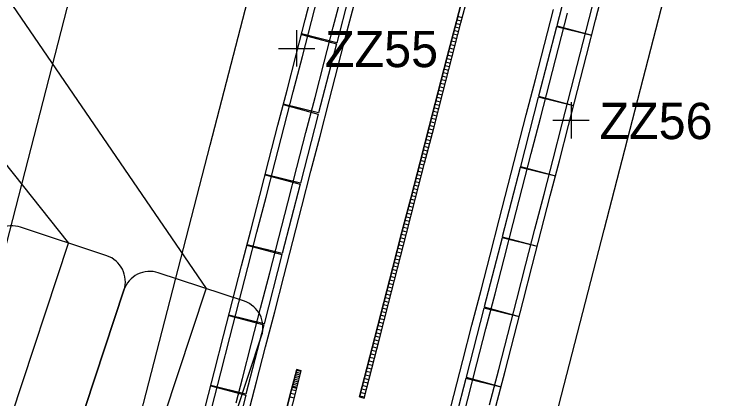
# Model space of a CAD drawing. Extents: x -733601 to -733291, y -1137892 to -1137187.
# Drawn here: x -733444.38 to -733424.52, y -1137642.25 to -1137631.66 of the extents above; entities that cross this region are included whole.
import ezdxf

# ---------------------------------------------------------------- set-up
doc = ezdxf.new("R2010")
doc.units = 0
for name, color, linetype in [('BP_ZBP_a_ZZ', 7, 'Continuous'), ('Default', 7, 'Continuous'), ('SIT_PROJ', 7, 'Continuous'), ('SIT_PUV_ZELEZNICE', 7, 'Continuous')]:
    doc.layers.add(name, color=color, linetype=linetype)

# ---------------------------------------------------------------- blocks, each defined once
blk = doc.blocks.new('T_PS_1_3')
at = {"layer": 'Default'}
blk.add_line((-12.486, 3.717), (12.486, 3.717), dxfattribs=at)
for points in [[(10.986, 8), (-10.986, 8)], [(-12.486, 6.5), (-12.486, 1.5)], [(12.486, 1.5), (12.486, 6.5)], [(-10.986, 0), (10.986, 0)]]:
    blk.add_lwpolyline(points, dxfattribs=at)
for centre, start, end in [((-10.986, 6.5), 90, 180), ((10.986, 6.5), 0, 90), ((-10.986, 1.5), 180, 270), ((10.986, 1.5), 270, 360)]:
    blk.add_arc(centre, 1.5, start, end, dxfattribs=at)
blk.add_text('SO', height=2.7, dxfattribs=at).set_placement((-11.75, 4.466))
blk = doc.blocks.new('T_PS_1_1_5')
at = {"layer": 'Default'}
blk.add_line((-12.486, 3.717), (12.486, 3.717), dxfattribs=at)
for points in [[(10.986, 8), (-10.986, 8)], [(-12.486, 6.5), (-12.486, 1.5)], [(12.486, 1.5), (12.486, 6.5)], [(-10.986, 0), (10.986, 0)]]:
    blk.add_lwpolyline(points, dxfattribs=at)
for centre, start, end in [((-10.986, 6.5), 90, 180), ((10.986, 6.5), 0, 90), ((-10.986, 1.5), 180, 270), ((10.986, 1.5), 270, 360)]:
    blk.add_arc(centre, 1.5, start, end, dxfattribs=at)
blk.add_text('SO', height=2.7, dxfattribs=at).set_placement((-11.75, 4.466))

msp = doc.modelspace()

# ---------------------------------------------------------------- linework, layer by layer
at = {"layer": 'BP_ZBP_a_ZZ'}
for p, q in [((-733436.599, -1137632.096), (-733436.599, -1137633.096)), ((-733437.099, -1137632.596), (-733436.099, -1137632.596)), ((-733429.027, -1137634.079), (-733429.027, -1137635.079)), ((-733429.527, -1137634.579), (-733428.527, -1137634.579))]:
    msp.add_line(p, q, dxfattribs=at)
at = {"layer": 'SIT_PROJ'}
for points in [[(-733455.227, -1137615.669), (-733439.093, -1137639.217), (-733439.093, -1137639.217)], [(-733457.665, -1137619.387), (-733442.89, -1137637.96), (-733442.89, -1137637.96)]]:
    msp.add_lwpolyline(points, dxfattribs=at)
at = {"layer": 'SIT_PUV_ZELEZNICE'}
for p, q in [((-733428.932, -1137630.069), (-733429.425, -1137631.976)), ((-733434.999, -1137630.535), (-733435.494, -1137632.442)), ((-733432.029, -1137631.753), (-733432.155, -1137631.72)), ((-733432.08, -1137631.946), (-733432.205, -1137631.914)), ((-733432.055, -1137631.849), (-733432.18, -1137631.817)), ((-733429.425, -1137631.976), (-733428.459, -1137632.236)), ((-733432.13, -1137632.14), (-733432.256, -1137632.107)), ((-733432.105, -1137632.043), (-733432.231, -1137632.011)), ((-733429.432, -1137632.005), (-733429.925, -1137633.913)), ((-733428.461, -1137632.246), (-733429.432, -1137632.005)), ((-733436.467, -1137632.21), (-733435.501, -1137632.47)), ((-733435.494, -1137632.442), (-733436.464, -1137632.2)), ((-733432.205, -1137632.43), (-733432.331, -1137632.398)), ((-733432.18, -1137632.334), (-733432.306, -1137632.301)), ((-733432.155, -1137632.237), (-733432.281, -1137632.204)), ((-733435.501, -1137632.47), (-733435.995, -1137634.377)), ((-733432.255, -1137632.624), (-733432.381, -1137632.591)), ((-733432.23, -1137632.527), (-733432.356, -1137632.495)), ((-733432.305, -1137632.818), (-733432.431, -1137632.785)), ((-733432.28, -1137632.721), (-733432.406, -1137632.688)), ((-733432.355, -1137633.011), (-733432.481, -1137632.979)), ((-733432.33, -1137632.914), (-733432.456, -1137632.882)), ((-733432.405, -1137633.205), (-733432.531, -1137633.172)), ((-733432.38, -1137633.108), (-733432.506, -1137633.076)), ((-733432.455, -1137633.398), (-733432.581, -1137633.366)), ((-733432.43, -1137633.302), (-733432.556, -1137633.269)), ((-733432.506, -1137633.592), (-733432.631, -1137633.56)), ((-733432.481, -1137633.495), (-733432.606, -1137633.463)), ((-733432.556, -1137633.786), (-733432.682, -1137633.753)), ((-733432.531, -1137633.689), (-733432.657, -1137633.656)), ((-733432.606, -1137633.979), (-733432.732, -1137633.947)), ((-733432.581, -1137633.882), (-733432.707, -1137633.85)), ((-733429.932, -1137633.942), (-733430.425, -1137635.849)), ((-733428.962, -1137634.182), (-733429.932, -1137633.942)), ((-733429.925, -1137633.913), (-733428.959, -1137634.172)), ((-733436.968, -1137634.146), (-733436.003, -1137634.406)), ((-733435.995, -1137634.377), (-733436.966, -1137634.136)), ((-733432.656, -1137634.173), (-733432.782, -1137634.14)), ((-733432.631, -1137634.076), (-733432.757, -1137634.044)), ((-733432.706, -1137634.367), (-733432.832, -1137634.334)), ((-733432.681, -1137634.27), (-733432.807, -1137634.237)), ((-733436.003, -1137634.406), (-733436.496, -1137636.313)), ((-733432.756, -1137634.56), (-733432.882, -1137634.528)), ((-733432.731, -1137634.463), (-733432.857, -1137634.431)), ((-733432.806, -1137634.754), (-733432.932, -1137634.721)), ((-733432.781, -1137634.657), (-733432.907, -1137634.625)), ((-733432.856, -1137634.947), (-733432.982, -1137634.915)), ((-733432.831, -1137634.851), (-733432.957, -1137634.818)), ((-733432.906, -1137635.141), (-733433.032, -1137635.109)), ((-733432.881, -1137635.044), (-733433.007, -1137635.012)), ((-733432.956, -1137635.335), (-733433.082, -1137635.302)), ((-733432.931, -1137635.238), (-733433.057, -1137635.205)), ((-733433.006, -1137635.528), (-733433.132, -1137635.496)), ((-733432.981, -1137635.432), (-733433.107, -1137635.399)), ((-733433.057, -1137635.722), (-733433.182, -1137635.689)), ((-733433.032, -1137635.625), (-733433.157, -1137635.593)), ((-733433.107, -1137635.916), (-733433.233, -1137635.883)), ((-733433.082, -1137635.819), (-733433.207, -1137635.786)), ((-733430.433, -1137635.878), (-733430.925, -1137637.786)), ((-733429.462, -1137636.119), (-733430.433, -1137635.878)), ((-733430.425, -1137635.849), (-733429.459, -1137636.109)), ((-733437.469, -1137636.082), (-733436.504, -1137636.342)), ((-733436.496, -1137636.313), (-733437.467, -1137636.072)), ((-733433.157, -1137636.109), (-733433.283, -1137636.077)), ((-733433.132, -1137636.012), (-733433.258, -1137635.98)), ((-733436.504, -1137636.342), (-733436.996, -1137638.249)), ((-733433.232, -1137636.4), (-733433.358, -1137636.367)), ((-733433.207, -1137636.303), (-733433.333, -1137636.27)), ((-733433.182, -1137636.206), (-733433.308, -1137636.174)), ((-733433.282, -1137636.593), (-733433.408, -1137636.561)), ((-733433.257, -1137636.496), (-733433.383, -1137636.464)), ((-733433.332, -1137636.787), (-733433.458, -1137636.754)), ((-733433.307, -1137636.69), (-733433.433, -1137636.658)), ((-733433.382, -1137636.981), (-733433.508, -1137636.948)), ((-733433.357, -1137636.884), (-733433.483, -1137636.851)), ((-733433.432, -1137637.174), (-733433.558, -1137637.142)), ((-733433.407, -1137637.077), (-733433.533, -1137637.045)), ((-733433.482, -1137637.368), (-733433.608, -1137637.335)), ((-733433.457, -1137637.271), (-733433.583, -1137637.239)), ((-733433.532, -1137637.561), (-733433.658, -1137637.529)), ((-733433.507, -1137637.465), (-733433.633, -1137637.432)), ((-733433.582, -1137637.755), (-733433.708, -1137637.723)), ((-733433.557, -1137637.658), (-733433.683, -1137637.626)), ((-733433.632, -1137637.949), (-733433.758, -1137637.916)), ((-733433.607, -1137637.852), (-733433.733, -1137637.819)), ((-733430.933, -1137637.815), (-733431.425, -1137639.722)), ((-733429.962, -1137638.055), (-733430.933, -1137637.815)), ((-733430.925, -1137637.786), (-733429.96, -1137638.045)), ((-733437.97, -1137638.018), (-733437.004, -1137638.278)), ((-733436.996, -1137638.249), (-733437.967, -1137638.009)), ((-733433.682, -1137638.142), (-733433.808, -1137638.11)), ((-733433.657, -1137638.046), (-733433.783, -1137638.013)), ((-733437.004, -1137638.278), (-733437.496, -1137640.186)), ((-733433.732, -1137638.336), (-733433.858, -1137638.304)), ((-733433.707, -1137638.239), (-733433.833, -1137638.207)), ((-733433.782, -1137638.53), (-733433.908, -1137638.497)), ((-733433.757, -1137638.433), (-733433.883, -1137638.4)), ((-733433.832, -1137638.723), (-733433.958, -1137638.691)), ((-733433.807, -1137638.626), (-733433.933, -1137638.594)), ((-733433.882, -1137638.917), (-733434.008, -1137638.884)), ((-733433.857, -1137638.82), (-733433.983, -1137638.788)), ((-733433.932, -1137639.111), (-733434.058, -1137639.078)), ((-733433.907, -1137639.014), (-733434.033, -1137638.981)), ((-733433.982, -1137639.304), (-733434.108, -1137639.272)), ((-733433.957, -1137639.207), (-733434.083, -1137639.175)), ((-733434.032, -1137639.498), (-733434.158, -1137639.465)), ((-733434.007, -1137639.401), (-733434.133, -1137639.369)), ((-733434.082, -1137639.692), (-733434.208, -1137639.659)), ((-733434.057, -1137639.595), (-733434.183, -1137639.562)), ((-733431.425, -1137639.722), (-733430.46, -1137639.982)), ((-733437.496, -1137640.186), (-733438.467, -1137639.945)), ((-733434.132, -1137639.885), (-733434.258, -1137639.853)), ((-733434.107, -1137639.788), (-733434.233, -1137639.756)), ((-733431.433, -1137639.751), (-733431.926, -1137641.658)), ((-733430.462, -1137639.992), (-733431.433, -1137639.751)), ((-733438.47, -1137639.955), (-733437.504, -1137640.214)), ((-733434.207, -1137640.176), (-733434.333, -1137640.143)), ((-733434.182, -1137640.079), (-733434.308, -1137640.046)), ((-733434.157, -1137639.982), (-733434.283, -1137639.95)), ((-733437.504, -1137640.214), (-733437.996, -1137642.122)), ((-733434.258, -1137640.369), (-733434.383, -1137640.337)), ((-733434.233, -1137640.272), (-733434.358, -1137640.24)), ((-733434.308, -1137640.563), (-733434.433, -1137640.53)), ((-733434.283, -1137640.466), (-733434.408, -1137640.434)), ((-733434.358, -1137640.757), (-733434.483, -1137640.724)), ((-733434.333, -1137640.66), (-733434.458, -1137640.627)), ((-733434.408, -1137640.95), (-733434.533, -1137640.918)), ((-733434.383, -1137640.853), (-733434.508, -1137640.821)), ((-733434.458, -1137641.144), (-733434.583, -1137641.111)), ((-733434.433, -1137641.047), (-733434.558, -1137641.015)), ((-733434.508, -1137641.338), (-733434.633, -1137641.305)), ((-733434.483, -1137641.241), (-733434.608, -1137641.208)), ((-733436.49, -1137641.55), (-733436.616, -1137641.517)), ((-733436.478, -1137641.501), (-733436.603, -1137641.469)), ((-733436.597, -1137641.445), (-733436.471, -1137641.477)), ((-733434.558, -1137641.531), (-733434.683, -1137641.499)), ((-733434.533, -1137641.434), (-733434.658, -1137641.402)), ((-733436.54, -1137641.743), (-733436.666, -1137641.711)), ((-733436.528, -1137641.695), (-733436.653, -1137641.662)), ((-733436.515, -1137641.646), (-733436.641, -1137641.614)), ((-733436.503, -1137641.598), (-733436.628, -1137641.565)), ((-733434.608, -1137641.725), (-733434.733, -1137641.692)), ((-733434.583, -1137641.628), (-733434.708, -1137641.596)), ((-733431.933, -1137641.688), (-733432.426, -1137643.595)), ((-733430.962, -1137641.928), (-733431.933, -1137641.688)), ((-733431.926, -1137641.658), (-733430.96, -1137641.918)), ((-733438.969, -1137641.892), (-733438.003, -1137642.151)), ((-733437.996, -1137642.122), (-733438.966, -1137641.882)), ((-733436.722, -1137641.929), (-733436.596, -1137641.961)), ((-733436.59, -1137641.937), (-733436.716, -1137641.904)), ((-733436.577, -1137641.888), (-733436.703, -1137641.856)), ((-733436.565, -1137641.84), (-733436.691, -1137641.808)), ((-733436.553, -1137641.792), (-733436.678, -1137641.759)), ((-733434.658, -1137641.918), (-733434.783, -1137641.886)), ((-733434.633, -1137641.822), (-733434.758, -1137641.789)), ((-733436.641, -1137642.133), (-733436.766, -1137642.101)), ((-733436.616, -1137642.036), (-733436.741, -1137642.004)), ((-733434.708, -1137642.112), (-733434.833, -1137642.08)), ((-733434.683, -1137642.015), (-733434.808, -1137641.983)), ((-733438.003, -1137642.151), (-733438.494, -1137644.058)), ((-733436.666, -1137642.23), (-733436.791, -1137642.197)), ((-733434.866, -1137642.201), (-733434.74, -1137642.233)), ((-733434.865, -1137642.201), (-733434.739, -1137642.233)), ((-733434.733, -1137642.209), (-733434.858, -1137642.176))]:
    msp.add_line(p, q, dxfattribs=at)
for points in [[(-733459.36, -1137757.582), (-733458.338, -1137753.729), (-733455.783, -1137744.061), (-733453.237, -1137734.391), (-733450.698, -1137724.719), (-733448.167, -1137715.044), (-733445.645, -1137705.368), (-733443.13, -1137695.689), (-733440.624, -1137686.008), (-733440.158, -1137684.204), (-733438.123, -1137676.326), (-733435.622, -1137666.644), (-733433.121, -1137656.962), (-733430.62, -1137647.279), (-733428.119, -1137637.597), (-733425.618, -1137627.915), (-733423.422, -1137619.411), (-733423.117, -1137618.233), (-733420.616, -1137608.551), (-733418.11, -1137598.87), (-733415.599, -1137589.19), (-733413.078, -1137579.513), (-733412.782, -1137578.384)], [(-733469.582, -1137755.14), (-733468.663, -1137751.534), (-733466.195, -1137741.843), (-733463.726, -1137732.153), (-733461.257, -1137722.462), (-733458.789, -1137712.772), (-733456.32, -1137703.081), (-733453.852, -1137693.391), (-733451.383, -1137683.701), (-733451.044, -1137682.371), (-733448.914, -1137674.01), (-733446.443, -1137664.32), (-733443.966, -1137654.632), (-733441.48, -1137644.946), (-733438.982, -1137635.263), (-733436.47, -1137625.584), (-733433.94, -1137615.909), (-733431.39, -1137606.239), (-733431.038, -1137604.913), (-733428.815, -1137596.577), (-733426.217, -1137586.92), (-733424.808, -1137581.736)], [(-733473.591, -1137751.638), (-733472.603, -1137747.76), (-733470.135, -1137738.069), (-733467.666, -1137728.379), (-733465.198, -1137718.688), (-733462.729, -1137708.998), (-733460.26, -1137699.307), (-733457.792, -1137689.617), (-733455.323, -1137679.926), (-733452.855, -1137670.236), (-733450.386, -1137660.545), (-733448.734, -1137654.061), (-733447.917, -1137650.855), (-733445.432, -1137641.168), (-733442.928, -1137631.487), (-733440.405, -1137621.811), (-733437.862, -1137612.139), (-733437.8, -1137611.906), (-733435.314, -1137602.469), (-733432.775, -1137592.797), (-733432.613, -1137592.177)], [(-733439.115, -1137642.457), (-733438.865, -1137641.489), (-733438.616, -1137640.521), (-733438.366, -1137639.553), (-733438.116, -1137638.585), (-733437.866, -1137637.617), (-733437.616, -1137636.649), (-733437.365, -1137635.681), (-733437.115, -1137634.713), (-733436.864, -1137633.745), (-733436.614, -1137632.777), (-733436.363, -1137631.81), (-733436.112, -1137630.842)], [(-733438.94, -1137642.502), (-733438.691, -1137641.534), (-733438.441, -1137640.566), (-733438.192, -1137639.598), (-733437.942, -1137638.63), (-733437.692, -1137637.662), (-733437.441, -1137636.694), (-733437.191, -1137635.726), (-733436.941, -1137634.758), (-733436.69, -1137633.79), (-733436.439, -1137632.822), (-733436.189, -1137631.855), (-733435.937, -1137630.887)], [(-733431.941, -1137630.892), (-733432.191, -1137631.859), (-733432.442, -1137632.827), (-733432.692, -1137633.794), (-733432.942, -1137634.761), (-733433.192, -1137635.728), (-733433.443, -1137636.696), (-733433.693, -1137637.663), (-733433.943, -1137638.63), (-733434.192, -1137639.598), (-733434.442, -1137640.565), (-733434.865, -1137642.201), (-733434.74, -1137642.233), (-733434.739, -1137642.233), (-733434.316, -1137640.598), (-733434.067, -1137639.63), (-733433.817, -1137638.663), (-733433.567, -1137637.695), (-733433.317, -1137636.728), (-733433.067, -1137635.761), (-733432.816, -1137634.793), (-733432.566, -1137633.826), (-733432.316, -1137632.859), (-733432.066, -1137631.892), (-733431.815, -1137630.925)], [(-733434.865, -1137642.201), (-733434.442, -1137640.565), (-733434.192, -1137639.598), (-733433.943, -1137638.63), (-733433.693, -1137637.663), (-733433.443, -1137636.696), (-733433.192, -1137635.728), (-733432.942, -1137634.761), (-733432.692, -1137633.794), (-733432.442, -1137632.827), (-733432.191, -1137631.859), (-733431.941, -1137630.892)], [(-733434.739, -1137642.233), (-733434.316, -1137640.598), (-733434.067, -1137639.63), (-733433.817, -1137638.663), (-733433.567, -1137637.695), (-733433.317, -1137636.728), (-733433.067, -1137635.761), (-733432.816, -1137634.793), (-733432.566, -1137633.826), (-733432.316, -1137632.859), (-733432.066, -1137631.892), (-733431.815, -1137630.925)], [(-733431.274, -1137642.414), (-733431.024, -1137641.447), (-733430.774, -1137640.48), (-733430.525, -1137639.513), (-733430.275, -1137638.546), (-733430.025, -1137637.58), (-733429.775, -1137636.613), (-733429.526, -1137635.646), (-733429.276, -1137634.679), (-733429.026, -1137633.712), (-733428.777, -1137632.746), (-733428.527, -1137631.779), (-733428.277, -1137630.812)], [(-733431.1, -1137642.459), (-733430.85, -1137641.492), (-733430.6, -1137640.525), (-733430.35, -1137639.558), (-733430.101, -1137638.591), (-733429.851, -1137637.625), (-733429.601, -1137636.658), (-733429.351, -1137635.691), (-733429.102, -1137634.724), (-733428.852, -1137633.757), (-733428.602, -1137632.791), (-733428.353, -1137631.824), (-733428.103, -1137630.857)], [(-733438.263, -1137642.358), (-733438.09, -1137641.688), (-733437.841, -1137640.72), (-733437.591, -1137639.753), (-733437.341, -1137638.785), (-733437.091, -1137637.817), (-733436.841, -1137636.849), (-733436.591, -1137635.881), (-733436.341, -1137634.913), (-733436.09, -1137633.946), (-733435.839, -1137632.978), (-733435.588, -1137632.01), (-733435.337, -1137631.043)], [(-733437.876, -1137642.458), (-733437.703, -1137641.788), (-733437.454, -1137640.82), (-733437.204, -1137639.852), (-733436.954, -1137638.885), (-733436.704, -1137637.917), (-733436.454, -1137636.949), (-733436.204, -1137635.981), (-733435.953, -1137635.014), (-733435.703, -1137634.046), (-733435.452, -1137633.078), (-733435.201, -1137632.111), (-733434.95, -1137631.143)], [(-733432.684, -1137643.796), (-733432.511, -1137643.126), (-733432.261, -1137642.159), (-733432.012, -1137641.192), (-733431.762, -1137640.225), (-733431.512, -1137639.258), (-733431.262, -1137638.291), (-733431.013, -1137637.324), (-733430.763, -1137636.358), (-733430.513, -1137635.391), (-733430.264, -1137634.424), (-733430.014, -1137633.457), (-733429.764, -1137632.491), (-733429.514, -1137631.524)], [(-733432.297, -1137643.896), (-733432.124, -1137643.226), (-733431.874, -1137642.259), (-733431.624, -1137641.292), (-733431.375, -1137640.325), (-733431.125, -1137639.358), (-733430.875, -1137638.391), (-733430.625, -1137637.425), (-733430.376, -1137636.458), (-733430.126, -1137635.491), (-733429.876, -1137634.524), (-733429.627, -1137633.557), (-733429.377, -1137632.591), (-733429.127, -1137631.624)], [(-733441.106, -1137659.005), (-733440.975, -1137658.493), (-733440.727, -1137657.525), (-733440.479, -1137656.557), (-733440.231, -1137655.588), (-733439.983, -1137654.62), (-733439.735, -1137653.651), (-733439.487, -1137652.683), (-733439.238, -1137651.715), (-733438.99, -1137650.747), (-733438.741, -1137649.778), (-733438.493, -1137648.81), (-733438.244, -1137647.842), (-733437.995, -1137646.874), (-733437.746, -1137645.906), (-733437.497, -1137644.938), (-733437.248, -1137643.97), (-733436.999, -1137643.002), (-733436.749, -1137642.034), (-733436.597, -1137641.445)], [(-733440.948, -1137658.912), (-733440.849, -1137658.526), (-733440.601, -1137657.557), (-733440.353, -1137656.589), (-733440.105, -1137655.62), (-733439.857, -1137654.652), (-733439.609, -1137653.684), (-733439.361, -1137652.715), (-733439.112, -1137651.747), (-733438.864, -1137650.779), (-733438.615, -1137649.811), (-733438.367, -1137648.843), (-733438.118, -1137647.874), (-733437.869, -1137646.906), (-733437.62, -1137645.938), (-733437.371, -1137644.97), (-733437.122, -1137644.002), (-733436.873, -1137643.035), (-733436.623, -1137642.067), (-733436.471, -1137641.477)], [(-733436.873, -1137643.035), (-733436.623, -1137642.067), (-733436.596, -1137641.961), (-733436.722, -1137641.929), (-733436.749, -1137642.034), (-733436.999, -1137643.002)]]:
    msp.add_lwpolyline(points, dxfattribs=at)
msp.add_lwpolyline([(-733436.471, -1137641.477), (-733436.597, -1137641.445), (-733436.722, -1137641.929), (-733436.596, -1137641.961)], close=True, dxfattribs=at)

# ---------------------------------------------------------------- block references
at = {"layer": 'SIT_PROJ', "xscale": 0.4999999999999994, "yscale": 0.49999999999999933, "rotation": 71.68988829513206}
for name, p in [('T_PS_1_3', (-733443.087, -1137644.471)), ('T_PS_1_1_5', (-733439.29, -1137645.728))]:
    msp.add_blockref(name, p, dxfattribs=at)

# ---------------------------------------------------------------- texts
at = {"layer": 'BP_ZBP_a_ZZ'}
for s, p in [('ZZ55', (-733435.818, -1137633.114)), ('ZZ56', (-733428.246, -1137635.097))]:
    msp.add_text(s, height=1, dxfattribs=at).set_placement(p)

doc.saveas('drawing.dxf')
